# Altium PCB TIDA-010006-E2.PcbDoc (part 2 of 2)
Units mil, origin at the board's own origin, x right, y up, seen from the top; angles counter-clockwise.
Board outline 2251.83 x 2520.68 mil, 2 copper layers (Top Layer, Bottom Layer), stack 62 mil thick; 89 components, 37 nets, 190 pads, 37 vias.
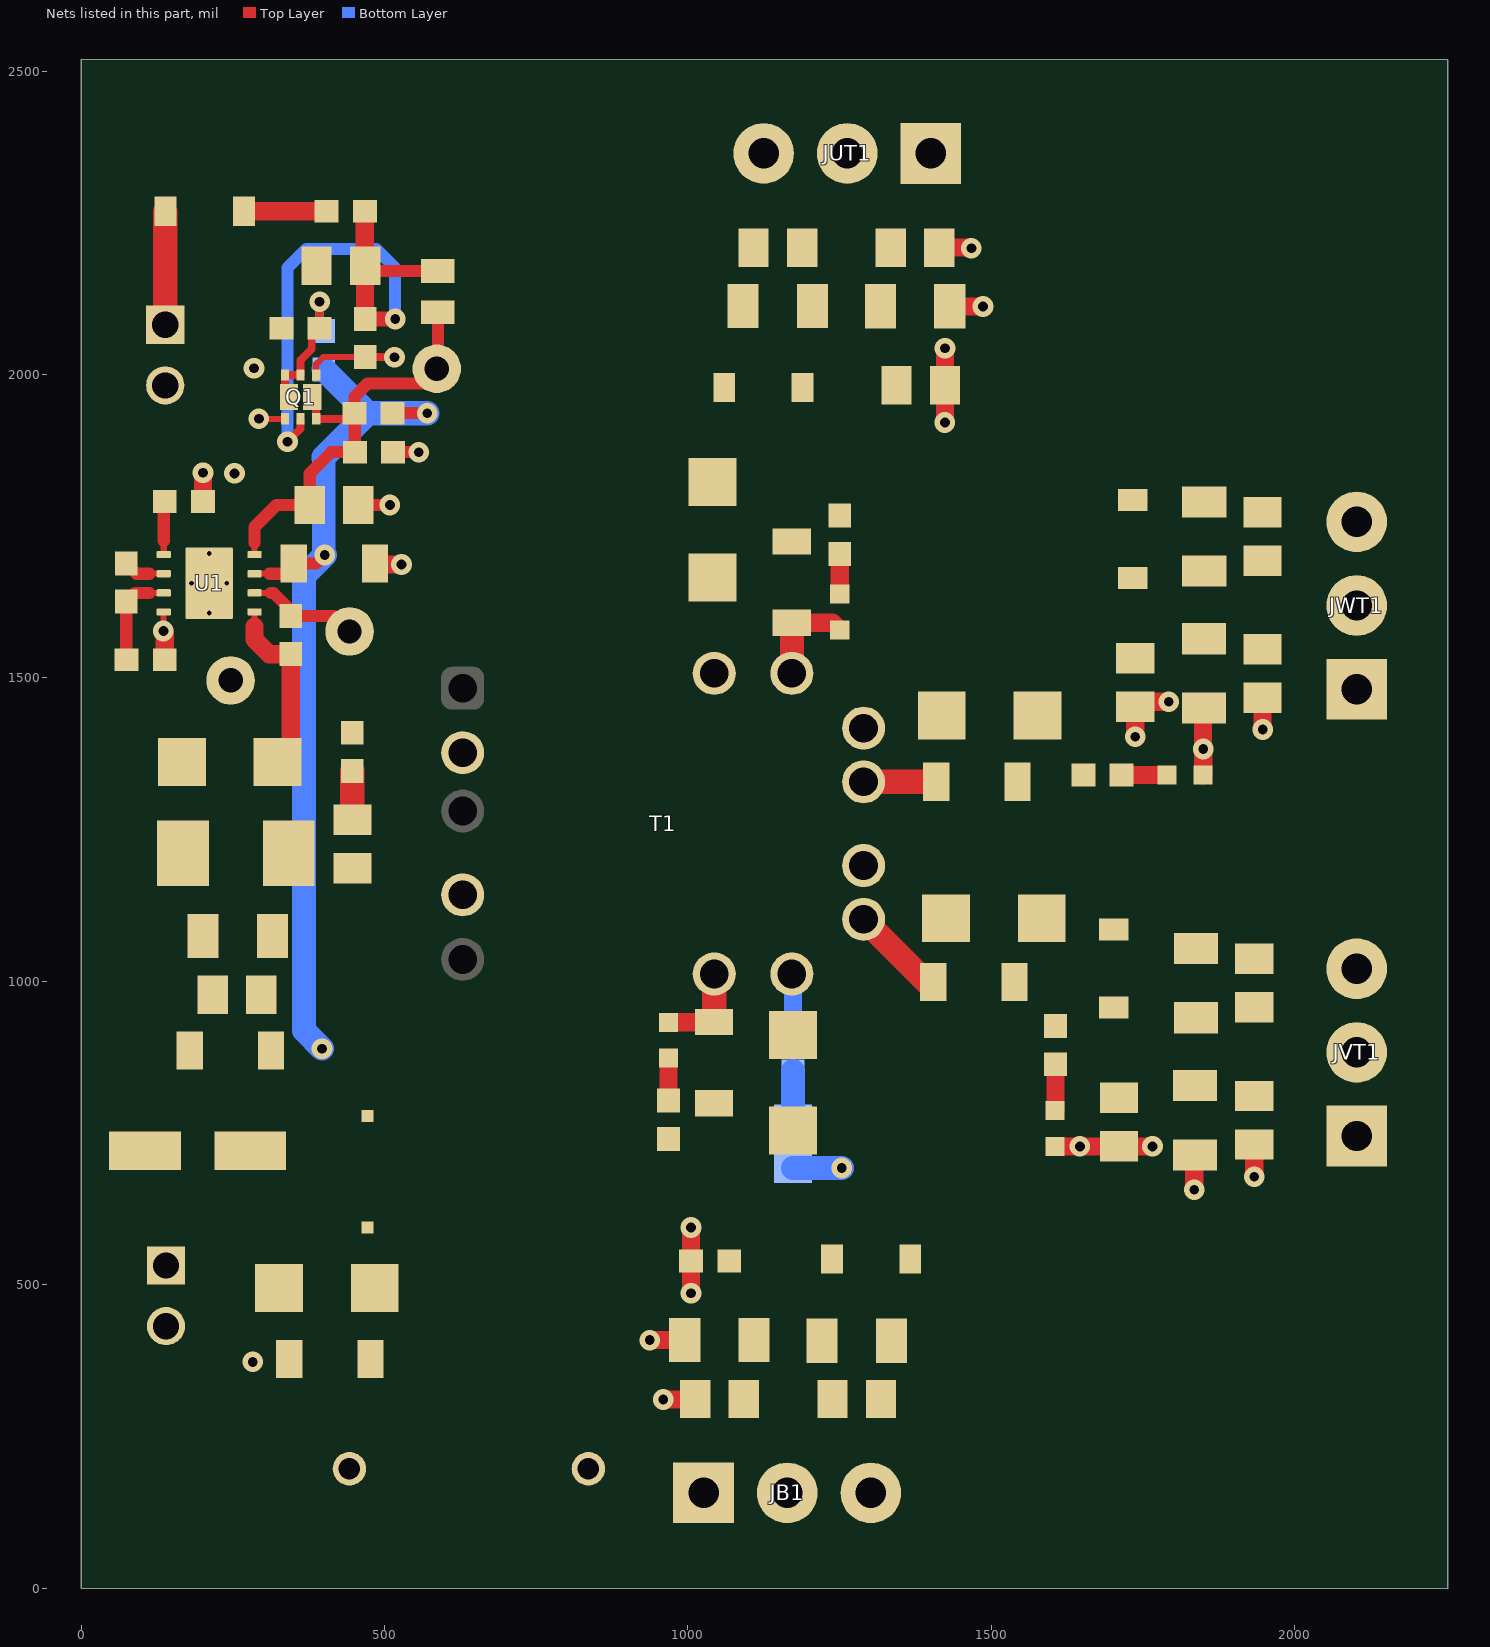
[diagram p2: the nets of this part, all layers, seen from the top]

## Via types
v1: diameter 34, hole 16, Top Layer to Bottom Layer, 33 vias
v2: diameter 19.68, hole 7.87, Top Layer to Bottom Layer, 4 vias

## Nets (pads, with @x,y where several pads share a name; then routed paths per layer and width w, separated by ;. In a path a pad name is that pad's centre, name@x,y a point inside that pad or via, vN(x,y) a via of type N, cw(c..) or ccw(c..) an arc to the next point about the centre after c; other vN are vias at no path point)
GND: C8.2 C9.2 C15.2 C25.2 C28.2 C29.2 C30.2 C31.2 J1.2 J2.2 Q1.1 Q1.4 R8.1 R12.1 R13.1 R19.2 TP3.1 U1.8 U1.9@211,1656 | length 469.6
  Top Layer w10: v1(135.63,1577.29) 135.63,1608.19 U1.8@136.2,1608.76 ; v1@293.02,1926.98 Q1.4@336.04,1926.98 ; Q1.1@387.22,1999.02 387.22,2017 398.72,2028.5 R19.2@468,2028.5
  Top Layer w13: R19.2@468,2028.5 v1(516.45,2028.5)
  Top Layer w20: R12.1@324.23,2070.09 R12.1@330.13,2076 ; C30.2@456.83,1785 v1(508.83,1785) ; R8.1@514,1872 v1(556.45,1872)
  Top Layer w30: v1(135.63,1577.29) 137.92,1575 R13.1@137.92,1530 ; C15.2@200.92,1790.63 v1(200.92,1838.13) ; C25.2@484.35,1688.63 485.98,1687 v1(528,1687)
  other v1: 283,373 252.8,1837 293,1927 284.87,2010.24
  other v2: 211,1606.79 181.87,1656 240.13,1656 211,1705.21
NetC6_1: C6.1 D3.1 D4.1 R3.2
NetC6_2: C6.2 C9.1 C25.1 C29.1 D4.2 L1.2 R3.1 R6.2 R9.2 R18.1 T1.4 U1.3 | length 1489.8
  Top Layer w10: U1.3@285.8,1671.75 310.43,1671.75
  Top Layer w20: 310.43,1671.75 333.61,1671.75 C25.1@350.5,1688.63 387.43,1688.63 v1(401.43,1702.63) ; R6.2@513.33,1936.28 v1(570.36,1936.28)
  Bottom Layer w39: v1@400,1704.06 400,1862
  Bottom Layer w40: v1(397,889.26) 367.2,919.06 367.2,1668.41 v1(401.43,1702.63) v1@400,1704.06 ; 400,1862 400,1864.05 472.22,1936.28 ; R9.2@400,2008.5 472.22,1936.28 ; v1(570.36,1936.28) 472.22,1936.28
NetC8_1: C8.1 D5.1 L1.1
NetC15_1: C15.1 U1.5 | length 88.1
  Top Layer w10: U1.5@136.2,1703.24 136.2,1726
  Top Layer w20: 136.2,1726 136.2,1788.9 C15.1@137.93,1790.63
NetC26_1: C26.1 D2.2 T1.11 | length 95.4
  Bottom Layer w30: C26.1@1173,915 T1.11@1173,1010.41
NetC26_2: C26.2 R17.2 | length 79.5
  Bottom Layer w40: R17.2@1173,772.5 C26.2@1173,852.01
NetC27_1: C27.1 D3.2 R7.2 T1.2 U1.1 | length 321.6
  Top Layer w10: 285.8,1584.83 U1.1@285.8,1608.76
  Top Layer w30: 285.8,1584.83 285.8,1563.25 309.92,1539.13 R7.2@345.43,1539.13 345.43,1363.31 D3.2@323.74,1341.63
NetC27_2: C27.2 R18.2 | length 80.5
  Top Layer w40: R18.2@447,1266.26 C27.2@447,1346.76
NetC30_1: C30.1 Q1.6 Q1.7 R6.1 R8.2 R21.2 TP1.1 U1.4 | length 749.3
  Top Layer w10: U1.4@285.8,1703.24 285.8,1722.63
  Top Layer w13: Q1.7@380.72,1963 387.22,1956.5 Q1.6@387.22,1926.98 441.03,1926.98 R6.1@450.34,1936.28
  Top Layer w15: Q1.7@380.72,1951.6 Q1.7@380.72,1963
  Top Layer w20: 285.8,1722.63 285.8,1748.8 322,1785 C30.1@376.83,1785 376.83,1836.83 412,1872 R8.2@451.01,1872 451.01,1935.61 R6.1@450.34,1936.28 450.34,1963.34 472,1985 561.54,1985 TP1.1@586,2009.46 588,2011.46 R21.2@588,2102.35
NetC31_1: C31.1 Q1.5 R19.1 R20.1 R21.1 | length 971.8
  Top Layer w13: v1@340.1,1889.1 361.63,1910.63 Q1.5@361.63,1926.98
  Top Layer w20: C31.1@468,2179 476.54,2170.46 R21.1@588,2170.46
  Top Layer w25: C31.1@467.5,2179.5 C31.1@468,2179 ; R19.1@468,2091.5 v1(517.5,2091.5)
  Top Layer w30: C31.1@467.5,2179.5 R20.1@467.5,2269 ; R19.1@468,2091.5 C31.1@468,2179
  Bottom Layer w20: v1(340,1889) 340,2175.84 371.16,2207 485.9,2207 517.5,2175.4 v1(517.5,2091.5)
NetD5_2: D5.2 J1.1
NetD6_2: D6.2 T1.7
NetD8_2: D8.2 T1.13
NetD10_2: D10.2 T1.15
NetD12_1: D12.1 J2.1 | length 187.3
  Top Layer w25: D12.1@138.63,2268.37 D12.1@139.26,2269
  Top Layer w40: J2.1@138.63,2082 D12.1@138.63,2268.37
NetD12_2: D12.2 R20.2 | length 136.3
  Top Layer w30: D12.2@268.2,2269 R20.2@404.5,2269
NetLD1_2: LD1.2 R1.1 | length 68
  Top Layer w30: R1.1@968,803.5 LD1.2@968,871.53
NetLD2_2: LD2.2 R4.1 | length 66.2
  Top Layer w30: LD2.2@1250,1638.28 R4.1@1250,1704.5
NetLD3_2: LD3.2 R11.1 | length 76.7
  Top Layer w30: LD3.2@1605,787.02 1605.46,787.48 R11.1@1605.46,863.5
NetLD4_2: LD4.2 R15.1 | length 75
  Top Layer w30: R15.1@1714.5,1340 LD4.2@1789.47,1340
NetQ1_2: Q1.2 Q1.3 Q1.8 R9.1 R12.2 | length 252.4
  Top Layer w13: Q1.8@342.54,1963 336.04,1969.5 Q1.3@336.04,1999.02 Q1.2@361.63,1999.02 361.63,2023.63 380,2042 380,2062.87 R12.2@393.13,2076 393.13,2120.87 393,2120.75 v1(393,2120)
  Bottom Layer w13: v1(393,2120) 393,2080.5 392,2079.5 R9.1@400,2071.5
NetR7_1: R7.1 TP2.1 U1.2 | length 188.6
  Top Layer w10: U1.2@285.8,1640.25 312.43,1640.25
  Top Layer w20: 312.43,1640.25 316.83,1640.25 345.43,1611.65 R7.1@345.43,1602.13 416.93,1602.13 TP2.1@442.43,1576.63
NetR10_1: R10.1 R13.2 U1.7 | length 163.7
  Top Layer w10: 112.54,1640.25 U1.7@136.2,1640.25
  Top Layer w20: R13.2@74.93,1530 74.43,1530.5 R10.1@74.43,1625.67 89.01,1640.25 112.54,1640.25
NetR10_2: R10.2 U1.6 | length 68.8
  Top Layer w10: 112.54,1671.75 U1.6@136.2,1671.75
  Top Layer w20: R10.2@74.43,1688.66 91.34,1671.75 112.54,1671.75
REF_B: C1.2 C2.2 C4.1 C5.1 D1.2 JB1.2 R2.2
REF_U_T: C7.1 C10.2 C11.2 C14.1 D7.2 JUT1.2 R5.2
REF_V_T: C13.1 C16.2 C17.2 C20.1 D9.2 JVT1.2 R14.2
REF_W_T: C19.1 C21.2 C23.2 C24.1 D11.2 JWT1.2 R16.2
VCC_B: C1.1 C2.1 C3.1 D1.1 D2.1 JB1.3 R1.2 R17.1 | length 80.5
  Bottom Layer w40: R17.1@1173,692.5 v1(1253.5,692.5)
VCC_U_T: C10.1 C11.1 C12.1 D6.1 D7.1 JUT1.3 R4.2
VCC_V_T: C16.1 C17.1 C18.1 D8.1 D9.1 JVT1.3 R11.2
VCC_W_T: C21.1 C22.1 C23.1 D10.1 D11.1 JWT1.3 R15.2
VEE_B: C3.2 C4.2 C5.2 C28.1 JB1.1 LD1.1 R2.1 T1.6 | length 376.3
  Top Layer w30: v1(937,409) C5.2@994.61,409.06 C5.2@994.61,409.06 ; v1(959,311) 1004.65,311 C4.2@1011.7,318.06 ; LD1.1@968,932.53 1042.6,932.53 C3.2@1043,932.93 ; v1(1004.94,486.05) R2.1@1004.94,539.26 v1(1004.94,594.52)
  Top Layer w40: C3.2@1043,932.93 1043.25,933.18 T1.6@1043.25,1012.2
VEE_U_T: C7.2 C12.2 C14.2 JUT1.1 LD2.1 R5.1 T1.8 | length 374.9
  Top Layer w30: C12.2@1171,1591.07 1238.16,1591.07 LD2.1@1250,1579.23 ; C14.2@1414.22,2203.46 C14.2@1418.76,2208 ; C14.2@1414.22,2209 1466,2209 v1(1467,2208) ; v1(1423.31,1921) 1423.31,1982.09 R5.1@1423.49,1982.26 v1(1423.49,2043.09) ; C7.2@1441.15,2112.46 1441.61,2112 v1(1486,2112)
  Top Layer w40: T1.8@1171.2,1507.48 C12.2@1171.2,1571.67
VEE_V_T: C13.2 C18.2 C20.2 JVT1.1 LD3.1 R14.1 T1.12 | length 459.4
  Top Layer w30: C18.2@1392.68,999 1403.47,988.2 1403.47,998.4 C18.2@1404.07,999 ; LD3.1@1605,727.97 1645.64,727.97 v1(1645.79,728.11) R14.1@1710,728.11 v1(1765.26,728.11) ; v1(1834,656.57) C13.2@1834,709.17 ; C20.2@1926.2,731.2 C20.2@1933,724.41 ; v1(1933,678.17) C20.2@1933,724.41 ; C20.2@1933,731.2 C20.2@1933,724.41
  Top Layer w40: T1.12@1289.32,1102.36 1392.68,999 C18.2@1404.07,999
VEE_W_T: C19.2 C22.2 C24.2 JWT1.1 LD4.1 R16.1 T1.14 | length 395.5
  Top Layer w30: v1(1737,1403) 1737,1460.56 1736.8,1460.76 v1(1792.06,1460.76) ; LD4.1@1848.97,1339.28 v1(1848.97,1383.02) 1848.8,1389 1848.8,1439.39 C19.2@1850,1440.6 ; C24.2@1941,1467.53 C24.2@1946.8,1461.73 ; v1(1946.8,1415) C24.2@1946.8,1461.73 ; C24.2@1946.8,1467.53 C24.2@1946.8,1461.73
  Top Layer w40: T1.14@1289.32,1328.74 1408.81,1328.74 C22.2@1409.07,1329
pads on no net: LBL1.0 T1.1 T1.3 T1.5 U1.9@211,1626.28 U1.9@211,1685.72

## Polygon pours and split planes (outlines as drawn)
NetC26_1 on Top Layer "TOP_LAYER_NETC26_1_P252" (solid, remove dead copper, pour order 252): 1223,960 1223,873 1214.8,864.8 1135.2,864.8 1127,873 1127,952.96 1133,958.96 1133,1042 1143,1052 1196,1052 1209,1039 1209,974
NetD8_2 on Top Layer "TOP_LAYER_NETD8_2_P250" (solid, remove dead copper, pour order 250): 1251,1163 1260,1154 1370,1154 1382,1142 1382,1066 1389,1059 1468,1059 1475,1066 1475,1140 1387,1228 1263,1228 1251,1216
REF_W_T on Top Layer "TOP_LAYER_REF_W_T_P082" (solid, remove dead copper, pour order 82): 1729.99,1719.46 2021.54,1719.46 2068.54,1672.46 2139.54,1672.46 2165,1647 2165,1584 2145.46,1564.46 2086,1564.46 2037,1515.46 1692.53,1515.46 1692.53,1681.99
REF_V_T on Top Layer "TOP_LAYER_REF_V_T_P184" (solid, remove dead copper, pour order 184): 2138.06,935.97 2158.03,916 2158.03,848.03 2138,827.97 2039.97,827.97 1990.97,778.97 1676.03,778.97 1664.3,790.7 1664.3,966.77 1680.5,982.97 2007.03,982.97 2054.03,935.97
REF_B on Top Layer "TOP_LAYER_REF_B_P186" (solid, remove dead copper, pour order 186): 1263.63,592.27 1263.63,253.26 1216.63,206.26 1216.63,130.26 1190.63,104.26 1139.63,104.26 1108.63,135.26 1108.63,236.26 1059.63,285.26 1059.63,593.06 1066.63,600.06 1255.84,600.06
REF_U_T on Top Layer "TOP_LAYER_REF_U_T_P188" (solid, remove dead copper, pour order 188): 1162.29,1929.25 1162.29,2268.26 1209.29,2315.26 1209.29,2391.26 1235.29,2417.26 1286.29,2417.26 1317.29,2386.26 1317.29,2285.26 1366.29,2236.26 1366.29,1928.46 1359.29,1921.46 1170.08,1921.46
VCC_V_T on Top Layer "TOP_LAYER_VCC_V_T_P192" (solid, remove dead copper, pour order 192): 2134,968 2159,993 2159,1080 2074,1165 1551,1165 1543,1157 1543,1060 1514,1031 1514,968 1520,962 1565,962 1573,954 1572,953 1572,900 1636,900 1638.81,902.81 1638.81,977.33 1671.48,1010 2017,1010 2059,968
VCC_W_T on Top Layer "TOP_LAYER_VCC_W_T_P196" (solid, remove dead copper, pour order 196): 1678,1311 1649,1282 1517,1282 1511.43,1287.57 1511.43,1377.43 1532,1398 1532,1710 1716,1894 2131,1894 2160,1865 2160,1725.44 2140.56,1706 2072,1706 2030,1748 1715.94,1748 1678,1710.06
VCC_B on Top Layer "TOP_LAYER_VCC_B_P200" (solid, remove dead copper, pour order 200): 946,762 993,762 1005.6,774.6 1005.6,820.6 1015.57,830.57 1091.03,830.57 1300.43,830.57 1454,677 1454,185 1372,103 1273,103 1250,126 1250,181 1290,221 1290,603 1290,620 1259,651 955,651 937,669 937,753
NetD6_2 on Top Layer "TOP_LAYER_NETD6_2_P202" (solid, remove dead copper, pour order 202): 1074,1712 1087,1699 1087,1611 1080,1604 1080,1493 1058,1471 1028.26,1471 1005,1494.26 1005,1606.22 997,1614.22 997,1704 1005,1712
VCC_U_T on Top Layer "TOP_LAYER_VCC_U_T_P204" (solid, remove dead copper, pour order 204): 1292,1759.3 1276.6,1743.9 1227.84,1743.9 1216.63,1732.68 1216.63,1712.26 1205.37,1701 1128,1701 1068,1761 993.01,1761 976,1778.01 976,2313 1088,2425 1150,2425 1177,2398 1177,2335 1134,2292 1134,1900 1161,1873 1260.76,1873 1292,1841.76 1292,1784.54
GND on Top Layer "TOP_LAYER_GND_P224" (solid, remove dead copper, pour order 224): 225.49,2021.51 225.49,2189.49 246.5,2210.5 412.5,2210.5 413,2210 413,2143 401,2131 366,2131 354.43,2119.43 354.43,1999.63 321.43,1966.63 321.43,1816.63 313.43,1808.63 284.43,1808.63 250.43,1774.63 250.43,1549.74 289.43,1510.74 289.43,1466.63 269.8,1447 126,1447 99.43,1420.43 99.43,971.55 151.98,919 201,919 204,916 204,812.27 168.04,776.3 168.04,683.34 111.7,627 74.42,589.73 74.42,498.58 102,471 174,471 233,412 365.65,412 372.43,405.22 372.43,350.02 363,340.6 269.83,340.6 248.43,362 37.66,362 15.29,384.37 15.29,1961.5 74.43,2020.63 224.61,2020.63
NetD5_2 on Top Layer "TOP_LAYER_NETD5_2_P230" (solid, remove dead copper, pour order 230): 253.96,568 284.96,537 364,537 369,532 369,457 364,452 271,452 226,497 111,497 102.76,505.24 102.76,560.76 110,568
NetC8_1 on Top Layer "TOP_LAYER_NETC8_1_P232" (solid, remove dead copper, pour order 232): 367.67,657.47 581.53,657.47 592,647 592,375 552,335 464,335 439,360 439,531 403,567 370,567 354.43,582.57 354.43,644.23
NetC6_2 on Top Layer "TOP_LAYER_NETC6_2_P234" (solid, remove dead copper, pour order 234): 300,1267 384,1267 390,1261 390,1229 406,1213 531,1213 565,1179 649,1179 664,1164 664,1122 648,1106 531,1106 480,1055 480,876 531,825 558,825 580,803 580,710 556,686 222,686 215,693 215,779.77 271.43,836.2 271.42,1238.42
NetC6_1 on Top Layer "TOP_LAYER_NETC6_1_P236" (solid, remove dead copper, pour order 236): 243,948 243,1370 208,1405 130,1405 125,1400 125,1002 182,945 240,945
NetC27_1 on Top Layer "TOP_LAYER_NETC27_1_P238" (solid, remove dead copper, pour order 238): 377,1321 383,1327 383,1362 411,1390 547,1390 597,1340 647,1340 665,1358 665,1395 647,1413 603,1413 564,1452 324,1452 279,1407 279,1327 285,1321
NetD10_2 on Top Layer "TOP_LAYER_NETD10_2_P256" (solid, remove dead copper, pour order 256): 1465,1390.26 1448.31,1373.57 1392.83,1373.57 1385.83,1380.57 1269.93,1380.57 1252.83,1397.67 1252.83,1440.07 1268.34,1455.57 1349.84,1455.57 1377.26,1483 1458.78,1483 1465,1476.78
GND on Bottom Layer "BOTTOM_LAYER_GND_P178" (solid, remove dead copper, pour order 178): 627,2229 627,1642.26 490,1505.26 490,183 470,163 413.26,163 389,187.26 389,241 261,369 70.83,369 29,410.83 29,2171 127,2269 587,2269
VEE_B on Bottom Layer "BOTTOM_LAYER_VEE_B_P228" (solid, remove dead copper, pour order 228): 1083,80 1059,55 900,55 807,148 807,213 908,314 908,884 982,958 982,1034 999,1051 1067,1051 1083,1035
VEE_V_T on Bottom Layer "BOTTOM_LAYER_VEE_V_T_P210" (solid, remove dead copper, pour order 210): 1459.87,1128.87 1449.73,1139 1262,1139 1252,1129 1252,1071 1266,1057 1290,1057 1712,635 2192,635 2235,678 2235,788 2221,802 1786.73,802
VEE_U_T on Bottom Layer "BOTTOM_LAYER_VEE_U_T_P214" (solid, remove dead copper, pour order 214): 1508,1902 1207,1601 1207,1493 1186,1472 1157,1472 1124,1505 1124,1688 1346,1910 1346,2419 1356,2429 1459,2429 1508,2380
VEE_W_T on Bottom Layer "BOTTOM_LAYER_VEE_W_T_P248" (solid, remove dead copper, pour order 248): 1250,1354 1262,1366 1475,1366 1643,1534 2214,1534 2222,1526 2222,1378 2198,1354 1677.43,1354 1612.43,1289 1258,1289 1250,1297

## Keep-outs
Keep-Out Layer:
  text ".Layer_Name" at -551.43,-1455.86 h60

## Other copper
Top Layer:
  pour cut-out: 124.11,1614.76 115.43,1606.07 115.43,1508.11 106.61,1499.3 106.61,1499.44 99.43,1506.63 99.43,1608.09 106.1,1614.76
  pour cut-out: 169.61,1759.93 169.61,1630.04 154.34,1614.76 136.2,1614.76 136.2,1621.88 150.43,1636.1 150.43,1743.9 166.46,1759.93
  region net NetC27_1: 274.43,1614.76 296.29,1614.76 300.71,1610.35 300.71,1584.83 296.51,1580.63 274.43,1580.63 271.43,1583.63 271.43,1611.76
  text ".Layer_Name" at -551.43,-1455.86 h60
Bottom Layer:
  text ".Layer_Name" at -551.43,-1455.86 h60

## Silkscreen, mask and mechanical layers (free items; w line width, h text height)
Top Overlay:
  circle w6: c513,1481.53 r14.76
  lines w6: 495.27,1808 526.21,1808 529.57,1808 536.57,1801 ; 496.54,2121.02 504.02,2121.02 504.02,2122.02 510,2128 ; 510,1718.19 543.81,1718.19 553,1709 ; 541.81,1909.08 580.08,1909.08 586,1915 ; 543.53,1900.54 577.46,1900.54 584,1894 ; 954,349 977.7,349 ; 1454,2187 1488.22,2187 1493.76,2192.54 ; 1857,1606.79 1857,1615.69 1862.31,1621 1894,1621 ; 1863,643 1863,676.72 ; 1956,660 1971,675 1971,697.2 ; 1967,1397 1976,1406 1976,1431 ; 570,966.43 572.26,964.17 1367.87,964.17 1367.87,1551.57 1364.33,1555.12 572.99,1555.12 570,1552.13 570,966.43
  text "VCC_U_T" at 805,2339 h35
  text "VEE_U_T" at 1490,2336 h35
  text "VCC_W_T" at 2007,1844 h35
  text "VEE_W_T" at 1994,1348 h35
  text "VCC_V_T" at 2001,1103 h35
  text "+" at 314.07,783 h30
  text "VEE_V_T" at 1982,626 h35
  text "24V" at 41,606 h30 r90
  text "+" at 290,583 h30
  text "-" at 264,337 h30 r90
  text "GND" at 11,324 h30
  text "VEE_B" at 768,39 h35
  text "VCC_B" at 1394,39 h35
  text ".Layer_Name" at -551.43,-1455.86 h60
Bottom Overlay:
  text ".Layer_Name" at -551.43,-1455.86 h60
Top Paste:
  text ".Layer_Name" at -551.43,-1455.86 h60
Bottom Paste:
  text ".Layer_Name" at -551.43,-1455.86 h60
Top Solder:
  text ".Layer_Name" at -551.43,-1455.86 h60
  text ".Layer_Name" at -551.43,-1455.86 h60
Bottom Solder:
  text ".Layer_Name" at -551.43,-1455.86 h60
Drill Guide:
  text ".Layer_Name" at -551.43,-1455.86 h60
M1 Board Outline:
  the board outline again, w10
M2 Board Dimensions:
  rectangle: -1003.43,-997.37 -628.43,-872.37
  rectangle: -1128.43,-872.37 -1003.43,-747.37
  lines w7: -1128.43,-872.37 -128.43,-872.37 ; -1003.43,-997.37 -1003.43,-747.37 ; -878.43,-997.37 -878.43,-747.37 ; -628.43,-997.37 -628.43,-747.37 ; -378.43,-997.37 -378.43,-747.37 ; -1128.43,-997.37 -1128.43,-747.37 -128.43,-747.37 -128.43,-997.37 -1128.43,-997.37
M3 3D STEP Top:
  text ".Layer_Name" at -551.43,-1455.86 h60
M4 3D STEP Bottom:
  text ".Layer_Name" at -551.43,-1455.86 h60
M5 Assembly Top:
  lines w10: -1420.43,-1527.54 5179.57,-1527.54 ; -1420.43,-1324.2 5181.57,-1324.2 ; -1420.43,-1120.87 -1420.43,-1730.87 2584.57,-1730.87 5181.57,-1730.87 5181.57,-1120.87 -1419.93,-1120.87 -1419.93,-1730.87 155.57,-1730.87 ; 1044.57,-1730.87 1044.57,-1120.87 ; 2311.57,-1324.2 2311.57,-1120.87 ; 3151.57,-1324.2 3151.57,-1120.87 ; 3773.57,-1737.37 3773.57,-1534.54
  text "COMPONENTS MARKED 'DNP' SHOULD NOT BE POPULATED." at 25.07,-915.87 h25
  text "ASSEMBLY VARIANT:" at 24.57,-1031.37 h25
  text ".VariantName" at 1060.57,-1031.37 h25
  text "PCB VIEWED FROM TOP SIDE" at -1356.93,-1253.04 h25
  text "BOARD #:" at 1119.57,-1253.04 h25
  text ".PRJ_Number" at 1665.07,-1253.04 h25
  text "REV:" at 2509.57,-1253.04 h25
  text ".PCB_Rev" at 2801.07,-1253.04 h25
  text "SVN REV:" at 3347.57,-1253.04 h25
  text ".VersionControl_RevNumber" at 3853.57,-1253.04 h25
  text "TID #:" at 1119.57,-1456.37 h25
  text ".TID" at 1665.07,-1456.37 h25
  text ".Layer_Name" at -928,-1469 h25
  text "PLOT NAME =" at -1356.93,-1661.71 h25
  text ".plot_File_Name" at -551.43,-1661.71 h25
  text "GENERATED    :" at 1121.57,-1661.71 h25
  text ".Print_Date" at 1991.07,-1661.71 h25
  text ".Print_Time" at 2720.07,-1661.71 h25
  text "TEXAS INSTRUMENTS" at 3984.57,-1661.71 h25
M6 Assembly Bottom:
  lines w10: -1420.93,-1324.7 5181.07,-1324.7 ; -1418.93,-1528.04 5181.07,-1528.04 ; -12.93,-1737.87 -12.93,-1535.04 ; 609.07,-1324.7 609.07,-1121.37 ; 1449.07,-1324.7 1449.07,-1121.37 ; 2716.07,-1731.37 2716.07,-1121.37 ; 3605.07,-1731.37 5180.57,-1731.37 5180.57,-1121.37 -1420.93,-1121.37 -1420.93,-1731.37 1176.07,-1731.37 5181.07,-1731.37 5181.07,-1121.37
  text "COMPONENTS MARKED 'DNP' SHOULD NOT BE POPULATED." at 4973.57,-915.37 h60
  text ".VariantName" at 3929.57,-1031.37 h60
  text "ASSEMBLY VARIANT:" at 4968.57,-1031.37 h60
  text ".VersionControl_RevNumber" at -92.93,-1253.54 h60
  text "SVN REV:" at 413.07,-1253.54 h60
  text ".PCB_Rev" at 959.57,-1253.54 h60
  text "REV:" at 1251.07,-1253.54 h60
  text ".PRJ_Number" at 2095.57,-1253.54 h60
  text "BOARD #:" at 2641.07,-1253.54 h60
  text "PCB VIEWED FROM BOTTOM SIDE" at 5117.57,-1253.54 h60
  text ".TID" at 2095.57,-1456.87 h60
  text "TID #:" at 2641.07,-1456.87 h60
  text ".Layer_Name" at 4520,-1458 h60
  text "TEXAS INSTRUMENTS" at -223.93,-1662.21 h60
  text ".Print_Time" at 1040.57,-1662.21 h60
  text ".Print_Date" at 1769.57,-1662.21 h60
  text "GENERATED    :" at 2639.07,-1662.21 h60
  text ".plot_File_Name" at 4312.07,-1662.21 h60
  text "PLOT NAME =" at 5117.57,-1662.21 h60
M9 Title Sheet:
  drawing of 57 lines, arcs and shapes, not listed
  text "1" at -388.59,7439.13 h70
  text "2" at 2107.07,7439.13 h70
  text "3" at 4596.42,7439.13 h70
  text "4" at 7103.09,7439.13 h70
  text "5" at 9602.07,7439.13 h70
  text "6" at 12107.07,7439.13 h70
  text "A" at -1544.93,6296.13 h70
  text "A" at 13255.07,6296.13 h70
  text "B" at -1544.93,3916.13 h70
  text "B" at 13255.07,3916.13 h70
  text "C" at -1544.93,1541.13 h70
  text "C" at 13255.07,1541.13 h70
  text "PROJECT TITLE:" at 10215.07,-319.87 h45
  text ".PRJ_Title" at 10265.07,-453.2 h70
  text "DESIGNED FOR:" at 10215.07,-620.87 h45
  text ".PRJ_Customer" at 10265.07,-760.87 h70
  text "D" at -1544.93,-828.87 h70
  text "D" at 13255.07,-828.87 h70
  text "FILE NAME:" at 10215.07,-920.87 h45
  text ".PCB_File_Name_No_Path" at 10265.07,-1040.87 h70
  text "Texas Instruments (TI) and/or its licensors do not warrant the accuracy or completeness of this specification" at 5245.57,-1202.71 h45
  text "ENGINEER:" at 10215.07,-1210.87 h45
  text "LAYOUT BY:" at 11720.07,-1210.87 h45
  text "or any information contained therein. TI and/or its licensors do not warrant that this design will meet" at 5200.59,-1315.37 h45
  text ".PRJ_Engineer" at 10265.07,-1365.86 h70
  text ".PCB_Layout" at 11770.57,-1365.86 h70
  text "the specifications, will be suitable for your application or fit for any particular purpose, or will operate in" at 5200.59,-1428.04 h45
  text "ALTIUM DESIGNER VERSION:" at 11720.07,-1520.87 h45
  text "an implementation. TI and/or its licensors do not warrant that the design is production worthy. You should" at 5200.59,-1540.7 h45
  text "completely validate and test your design implementation to confirm the system functionality for your application." at 5245.57,-1653.37 h45
  text ".print_Scale" at 10265.07,-1654.2 h70
  text ".Application_BuildNumber" at 11770.57,-1654.2 h70
  text "1" at -388.59,-1860.87 h70
  text "2" at 2107.07,-1860.87 h70
  text "3" at 4596.42,-1860.87 h70
  text "4" at 7103.09,-1860.87 h70
  text "5" at 9602.07,-1860.87 h70
  text "6" at 12107.07,-1860.87 h70
M10 Fab Notes:
  drawing of 189 lines, arcs and shapes, not listed
  text "DESIGN INFORMATION" at 11253.59,5758.8 h60
  text "MIN. TRACK WIDTH:" at 10609.03,5626.68 h60
  text "10" at 11705.28,5626.68 h60
  text "MIL" at 11860.03,5626.68 h60
  text "MIN. CLEARANCE:" at 10609.03,5502.55 h60
  text "0.2" at 11645.28,5502.56 h60
  text "mm" at 11860.03,5502.55 h60
  text "19.685" at 11489.07,5382 h60
  text "MIN. VIA PAD SIZE:" at 10609.03,5378.43 h60
  text "MIL" at 11860.03,5378.43 h60
  text "0.05mm (2MIL)" at 11304.03,5248.53 h60
  text "MINIMUM ANNULAR RING" at 10279.8,5240.3 h60
  text "EXTERNAL" at 12012.03,5240.3 h60
  text "PER" at 10479.8,5130.18 h60
  text "IPC-D-275 CLASS 2 LEVEL C" at 10699.8,5130.17 h60
  text "MIL, HOLES" at 12188.03,5029.7 h60
  text "+/-" at 11795.57,5021.11 h60
  text "+/-" at 12649.57,5021.11 h60
  text "REGISTRATION TOLERANCES:" at 10279.8,5020.05 h60
  text "METAL" at 11479.57,5020.05 h60
  text "5" at 12055.78,5020.05 h60
  text "3" at 12888.78,5020.05 h60
  text "MIL" at 13005.03,5020.05 h60
  text "HOLE SIZE TOLERANCE (UNLESS OTHERWISE SPECIFIED):" at 10279.8,4921.73 h60
  text "+/-" at 12649.57,4918.86 h60
  text "3" at 12888.78,4917.8 h60
  text "MIL" at 13005.03,4917.8 h60
  text "MATERIAL:" at 10205.03,4780.15 h60
  text "FR-4 High Tg" at 11191.48,4651.63 h60
  text "X" at 11047.04,4643.64 h60
  text "FR-408" at 10626.04,4639.12 h60
  text "OTHER" at 12114.03,4639.12 h60
  text "63 MIL (1.6mm) +/-10%" at 10946.14,4496.09 h60
  text "X" at 10826.04,4493.64 h60
  text "THICKNESS:" at 10279.8,4487.87 h60
  text "OTHER" at 12231.03,4487.87 h60
  text "TOLERANCE:" at 10279.8,4349.55 h60
  text "X" at 11128.04,4349.55 h60
  text "ANSI IPC-6012 TYPE 3 CLASS 2" at 11306.05,4349.55 h60
  text "OTHER +/-" at 11306.03,4205.36 h60
  text "BOW & TWIST:" at 10279.8,4060.17 h60
  text "X" at 11128.04,4060.17 h60
  text "ANSI IPC-6012 TYPE 3 CLASS 2" at 11306.05,4060.17 h60
  text "OTHER +/-" at 11306.03,3913.48 h60
  text "DRILLING:" at 10205.03,3782.86 h60
  text "NC_DRILL FILES" at 11966.03,3677.67 h60
  text "REFERENCE:" at 10279.8,3673.73 h60
  text "X" at 10937.04,3673.64 h60
  text "AS SHOWN" at 11115.03,3673.73 h60
  text "X" at 11838.04,3673.73 h60
  text "OTHER" at 12264.03,3531.48 h60
  text "PTH COPPER THICKNESS:" at 10279.48,3527.95 h60
  text "X" at 11418.72,3527.95 h60
  text "20-30 um" at 11546.71,3527.95 h60
  text "BOARD FINISH:" at 10205.03,3380.36 h60
  text "SILKSCREEN:" at 10360.26,3270.23 h60
  text "X" at 11318.04,3270.23 h60
  text "TOP" at 11435.03,3270.23 h60
  text "X" at 11828.04,3270.23 h60
  text "BOTTOM" at 11946.03,3270.23 h60
  text "SILKSCREEN COLOR:" at 10360.26,3115.04 h60
  text "X" at 11317.04,3115.04 h60
  text "WHITE" at 11435.03,3115.04 h60
  text "OTHER" at 11946.03,3115.04 h60
  text "X" at 11448.04,2971.59 h60
  text "GREEN" at 11566.03,2971.59 h60
  text "OTHER" at 12184.03,2971.59 h60
  text "SOLDER RESIST COLOR:" at 10360.26,2964.73 h60
  text "X" at 11448.04,2817.34 h60
  text "MATTE" at 11566.03,2817.34 h60
  text "SEMI-GLOSS" at 12183.57,2816.7 h60
  text "IMMERSION GOLD (ENIG)" at 11266.03,2644.57 h60
  text "ENEPIG" at 12603.57,2637.35 h60
  text "SURFACE FINISH:" at 10205.03,2636.35 h60
  text "X" at 11088.04,2636.35 h60
  text "IMM. TIN/SILVER OR EQUIV" at 10534.57,2499.03 h60
  text "OTHER" at 11966.03,2495.1 h60
  text "ARRAY/PANEL:" at 10205.03,2339.72 h60
  text "CUT AND TRIM PER M1 BOARD OUTLINE" at 11266.03,2331.5 h60
  text "N.C. ROUTE" at 11266.03,2195.53 h60
  text "X" at 11954.04,2195.53 h60
  text "V. SCORE" at 12132.03,2195.53 h60
  text "CERTIFICATION:" at 10205.03,2066.4 h60
  text "MATERIALS AND WORKMANSHIP FOR ALL PCBS" at 10930.03,2066.4 h60
  text "TO MEET OR EXCEED THE REQUIREMENTS OF:" at 10930.03,1972.34 h60
  text "X" at 10567.54,1843.71 h60
  text "ANSI IPC-A-600F CLASS ->" at 10695.54,1843.71 h60
  text "X" at 12343.54,1843.71 h60
  text "2" at 12453.54,1843.71 h60
  text "1" at 12138.54,1842.21 h60
  text "3" at 12807.54,1842.21 h60
  text "X" at 11379.54,1696.02 h60
  text "RoHS" at 11507.54,1696.02 h60
  text "OTHER" at 12151.94,1696.02 h60
  text "PER ORDER" at 12549,1696.02 h60
  text "ALL BOARDS MUST MEET OR EXCEED UL94-V0 REQUIREMENTS." at 10232.57,1542.2 h60
  text "PCB MUST BEAR THE UL94V-0 UL REGISTERED MATERIAL ID NUMBER" at 10232.57,1426.13 h60
  text "ADDITIONAL REQUIREMENTS:" at 10205.03,1256.71 h60
  text "MICROSECTION:" at 10279.8,1149.58 h60
  text "YES" at 11185.54,1149.58 h60
  text "REQUIRED" at 12047.03,1005.25 h60
  text "BARE BOARD ELEC. TEST:" at 10279.8,1002.39 h60
  text "NONE" at 11585.54,1002.39 h60
  text "X" at 11929.04,1002.39 h60
  text "PER ORDER" at 12639.03,1002.39 h60
  text "XX MIL VIAS REQUIRE NON-CONDUCTIVE FILL AND PLANARIZE" at 10447.95,797.45 h59
  text "XX MIL VIAS REQUIRE CONDUCTIVE FILL AND PLANARIZE" at 10455.95,693.47 h60
  text "OUTER XX MIL TRACES REQUIRE 50 OHM SINGLE-ENDED IMPEDANCE" at 10454.97,530.09 h58
  text "LAYER 2 & 3 (INNER LAYERS) XX MIL WIDE, XX MIL SPACE / TRACES REQUIRE 100 OHM DIFFERENTIAL IMPEDANCE" at 10446.97,294.37 h60
M11 Gerber Information:
  lines w10: -1420.43,-1527.54 5179.57,-1527.54 ; -1420.43,-1324.2 5181.57,-1324.2 ; -1420.43,-1120.87 -1420.43,-1730.87 2584.57,-1730.87 5181.57,-1730.87 5181.57,-1120.87 -1419.93,-1120.87 -1419.93,-1730.87 155.57,-1730.87 ; 1044.57,-1730.87 1044.57,-1120.87 ; 2311.57,-1324.2 2311.57,-1120.87 ; 3151.57,-1324.2 3151.57,-1120.87 ; 3773.57,-1737.37 3773.57,-1534.54
  text "ALL ARTWORK VIEWED FROM TOP SIDE" at -1356.93,-1253.04 h60
  text "BOARD #:" at 1119.57,-1253.04 h60
  text ".PRJ_Number" at 1665.07,-1253.04 h60
  text "REV:" at 2509.57,-1253.04 h60
  text ".PCB_Rev" at 2801.07,-1253.04 h60
  text "SVN REV:" at 3347.57,-1253.04 h60
  text ".VersionControl_RevNumber" at 3853.57,-1253.04 h60
  text "LAYER NAME =" at -1356.93,-1455.86 h60
  text "TID #:" at 1119.57,-1456.37 h60
  text ".TID" at 1665.07,-1456.37 h60
  text "PLOT NAME =" at -1356.93,-1661.71 h60
  text ".plot_File_Name" at -551.43,-1661.71 h60
  text "GENERATED    :" at 1121.57,-1661.71 h60
  text ".Print_Date" at 1991.07,-1661.71 h60
  text ".Print_Time" at 2720.07,-1661.71 h60
  text "TEXAS INSTRUMENTS" at 3984.57,-1661.71 h60
M12 Stackup:
  drawing of 191 lines, arcs and shapes, not listed
  text "Layer" at 8669.42,7075.13 h60
  text "Name" at 9079.33,7075.13 h60
  text "Material" at 10009.07,7075.13 h60
  text "Thickness" at 10868.84,7075.13 h60
  text "Constant" at 11518.68,7075.13 h60
  text "Board Layer Stack" at 12088.54,7075.13 h60
  text "1" at 8669.42,6955.13 h60
  text "Top Overlay" at 9079.33,6955.13 h60
  text "2" at 8669.42,6835.13 h60
  text "Top Solder" at 9079.33,6835.13 h60
  text "Solder Resist" at 10009.07,6835.13 h60
  text "0.40mil" at 10868.84,6835.13 h60
  text "3.5" at 11518.68,6835.13 h60
  text "3" at 8669.42,6715.13 h60
  text "Top Layer" at 9079.33,6715.13 h60
  text "Copper" at 10009.07,6715.13 h60
  text "1.40mil" at 10868.84,6715.13 h60
  text "4" at 8669.42,6595.13 h60
  text "Dielectric1" at 9079.33,6595.13 h60
  text "FR-4 High Tg" at 10009.07,6595.13 h60
  text "59.20mil" at 10868.84,6595.13 h60
  text "4.8" at 11518.68,6595.13 h60
  text "5" at 8669.42,6475.13 h60
  text "Bottom Layer" at 9079.33,6475.13 h60
  text "Copper" at 10009.07,6475.13 h60
  text "1.40mil" at 10868.84,6475.13 h60
  text "6" at 8669.42,6355.13 h60
  text "Bottom Solder" at 9079.33,6355.13 h60
  text "Solder Resist" at 10009.07,6355.13 h60
  text "0.40mil" at 10868.84,6355.13 h60
  text "3.5" at 11518.68,6355.13 h60
  text "7" at 8669.42,6235.13 h60
  text "Bottom Overlay" at 9079.33,6235.13 h60
M13 Component Bodies Top:
  text ".Layer_Name" at -551.43,-1455.86 h60
M14 Component Bodies Bottom:
  text ".Layer_Name" at -551.43,-1455.86 h60
M15 Courtyards Top:
  text ".Layer_Name" at -551.43,-1455.86 h60
M16 Courtyards Bottom:
  text ".Layer_Name" at -551.43,-1455.86 h60
Drill Drawing:
  circle w10: c4405.72,2140.68 r16.58
  circle w10: c4405.72,2140.68 r27.63
  lines w10: 4378.09,1988.74 4405.72,2002.55 4433.34,1988.74 4419.53,2016.36 4433.34,2043.99 4405.72,2030.18 4378.09,2043.99 4391.9,2016.36 4378.09,1988.74 ; 4378.09,2251.19 4391.9,2251.19 4391.9,2237.38 4419.53,2237.38 4419.53,2251.19 4433.34,2251.19 4433.34,2278.82 4419.53,2278.82 4419.53,2292.63 4391.9,2292.63 4391.9,2278.82 4378.09,2278.82 4378.09,2251.19 ; 4378.09,2361.7 4433.34,2361.7 4433.34,2416.95 4378.09,2416.95 4378.09,2361.7 ; 4378.09,2486.02 4433.34,2486.02 4433.34,2541.27 4378.09,2541.27 4378.09,2486.02 ; 4378.09,2637.96 4405.72,2610.34 4433.34,2637.96 4405.72,2665.59 4378.09,2637.96 ; 4378.09,2748.47 4391.9,2748.47 4405.72,2734.66 4419.53,2748.47 4433.34,2748.47 4419.53,2762.28 4433.34,2776.1 4419.53,2776.1 4405.72,2789.91 4391.9,2776.1 4378.09,2776.1 4391.9,2762.28 4378.09,2748.47 ; 4389.14,2497.07 4422.29,2497.07 4422.29,2530.22 4389.14,2530.22 4389.14,2497.07
  lines w12: 4328,1951.44 6306.02,1951.44 ; 4328,2821.68 6306.02,2821.68 ; 4665.86,1827.12 4665.86,2946 ; 4997.86,1827.12 4997.86,2946 ; 5634.43,1827.12 5634.43,2946 ; 5893.57,1827.12 5893.57,2946 ; 4328,1827.12 6306.02,1827.12 6306.02,2946 4328,2946 4328,1827.12
  text "Symbol" at 4402.59,2858.98 h72
  text "Quantity" at 4703.16,2858.98 h72
  text "Finished Hole Size" at 5035.16,2858.98 h72
  text "Plated" at 5671.72,2858.98 h72
  text "Hole Type" at 5930.86,2858.98 h72
  text "4" at 4703.16,2734.66 h60
  text "7.87mil (0.200mm)" at 5035.16,2734.66 h60
  text "PTH" at 5671.72,2734.66 h60
  text "Round" at 5930.86,2734.66 h60
  text "33" at 4703.16,2610.34 h60
  text "16.00mil (0.406mm)" at 5035.16,2610.34 h60
  text "PTH" at 5671.72,2610.34 h60
  text "Round" at 5930.86,2610.34 h60
  text "2" at 4703.16,2486.02 h60
  text "35.43mil (0.900mm)" at 5035.16,2486.02 h60
  text "PTH" at 5671.72,2486.02 h60
  text "Round" at 5930.86,2486.02 h60
  text "3" at 4703.16,2361.7 h60
  text "40.00mil (1.016mm)" at 5035.16,2361.7 h60
  text "PTH" at 5671.72,2361.7 h60
  text "Round" at 5930.86,2361.7 h60
  text "4" at 4703.16,2237.38 h60
  text "43.31mil (1.100mm)" at 5035.16,2237.38 h60
  text "PTH" at 5671.72,2237.38 h60
  text "Round" at 5930.86,2237.38 h60
  text "13" at 4703.16,2113.06 h60
  text "47.24mil (1.200mm)" at 5035.16,2113.06 h60
  text "PTH" at 5671.72,2113.06 h60
  text "Round" at 5930.86,2113.06 h60
  text "12" at 4703.16,1988.74 h60
  text "50.00mil (1.270mm)" at 5035.16,1988.74 h60
  text "PTH" at 5671.72,1988.74 h60
  text "Round" at 5930.86,1988.74 h60
  text "71 Total" at 4703.16,1864.42 h60
  text "Drill tolerances:" at 4226,1393.26 h60
  text "For 7.87mil drill via +0/-7.87 mil" at 4226,1243.26 h60
  text "For 16 mil drill via +0/-16 mil" at 4226,1099.26 h60
  text "For PTH +/- 3 mil" at 4226,955.26 h60
  text "NOTE:" at 4209,737 h60
  text "1. vias are non tented" at 4211,564 h60
  text "2. This not an impedance controlled board" at 4211,411.37 h60
  text ".Layer_Name" at -551.43,-1455.86 h60
M17 Embedded Cavity:
  text ".Layer_Name" at -551.43,-1455.86 h60
M18 Embedded Assembly:
  text ".Layer_Name" at -551.43,-1455.86 h60
M19 Embedded Keepout:
  text ".Layer_Name" at -551.43,-1455.86 h60

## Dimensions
-1128.43,-997.37 to -128.43,-997.37 on M2 Board Dimensions
2251.83,-1 to 0,0 on M2 Board Dimensions
0,0 to 0,2519.68 on M2 Board Dimensions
